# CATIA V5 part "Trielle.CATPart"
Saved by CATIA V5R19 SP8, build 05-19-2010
Part number: Trielle
Bounding box of the stored display mesh (mm): x -300 to 30, y 0 to 50, z -30 to 30
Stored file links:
  C:\Users\ThinkMotion\Desktop\EU_thinkMotion\iao\IAO_MMS_Groupe3\yschmidt\Train1434_yschmidt\Train1434_yschmidt\Trielle.CATPart
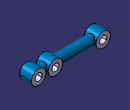
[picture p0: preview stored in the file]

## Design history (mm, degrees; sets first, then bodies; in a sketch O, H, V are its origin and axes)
Set1
  Point1: type OnCurve, Support edge [end face of Pad1 | face of Hole2], RefPoint {extremum Reference edge [end face of Pad1 | face of Hole2], Direction (1, 2, 3)}, Length 89.849
  Point2: type OnCurve, Support edge [face of Hole2 | start face of Pad1], RefPoint {extremum Reference edge [face of Hole2 | start face of Pad1], Direction (1, 2, 3)}, Length 87.899
  Line1: type Normal, LineFirstUpto edge [end face of Pad1 | face of Hole2], LineSecondUpto edge [face of Hole2 | start face of Pad1], RefPoint Point2, RefSkin zx-plane, Start 0, End 0
Body1 (main body)
  Sketch1 on zx-plane, origin (0, 0, 0), H (-1, 0, 0), V (0, 0, 1)
    circle A1 centre (0, 0) radius 30
    circle A2 centre (70, 0) radius 30
    point P1 (70, 0)
    circle A3 centre (270, 0) radius 30
    point P2 (270, 0)
    radius A3 = 30
    radius A2 = 30
    radius A1 = 30
    distance O P1 = 70
    distance P2 P1 = 200
    coincidence: P1 H, P2 H
  Pad1: profile Sketch1, direction (0, 1, 0), length 50
  Sketch2 on yz-plane, origin (0, 0, 0), H (0, 1, 0), V (0, 0, 1)
    circle A1 centre (25, 0) radius 20
    point P1 (25, 0)
    radius A1 = 20
    coincidence: P1 H
  Pad2: profile Sketch2, direction (-1, 0, 0), up to face of Pad1 from Sketch1.A3
  Sketch3 on end face of Pad1, origin (-209.6594, 50, -9.2267), H (1, 0, 0), V (0, 0, -1)
    point P1 (-60.3406, -9.2267)
    reference projected circle E1 centre (-60.3406, -9.2267) radius 30 from edge [face of Pad1 from Sketch1.A3 | end face of Pad1]
    concentricity: P1 E1
  Hole1: placed by Sketch3, at (-270, 50, 0) direction (0, -1, 0), diameter 30, through (limit type 6)
  Sketch4 on end face of Pad1, origin (-87.7513, 50, 0), H (1, 0, 0), V (0, 0, -1)
    point P1 (17.7513, 0)
    reference projected circle E1 centre (17.7513, 0) radius 30 from edge [face of Pad1 from Sketch1.A2 | end face of Pad1]
    concentricity: P1 E1
  Hole2: placed by Sketch4, at (-70, 50, 0) direction (0, -1, 0), diameter 30, through (limit type 6)
  Sketch5 on end face of Pad1, origin (6.1028, 50, 9.6712), H (1, 0, 0), V (0, 0, -1)
    point P1 (-6.1028, 9.6712)
    reference projected circle E1 centre (-6.1028, 9.6712) radius 30 from edge [face of Pad1 from Sketch1.A1 | end face of Pad1]
    concentricity: P1 E1
  Hole3: placed by Sketch5, at (0, 50, 0) direction (0, -1, 0), diameter 30, through (limit type 6)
